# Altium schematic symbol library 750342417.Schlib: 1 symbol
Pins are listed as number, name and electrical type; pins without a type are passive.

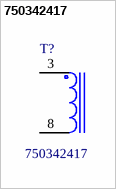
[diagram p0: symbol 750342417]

## 750342417
designator T?
TRANSFOERMER, 300uH, +/-10%, TH, 10-PIN; Manufacturer: WURTH ELEKTRONIK; CompType: TRANSFORMER; SymbolCreator: x0199378
pins: 3, 8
